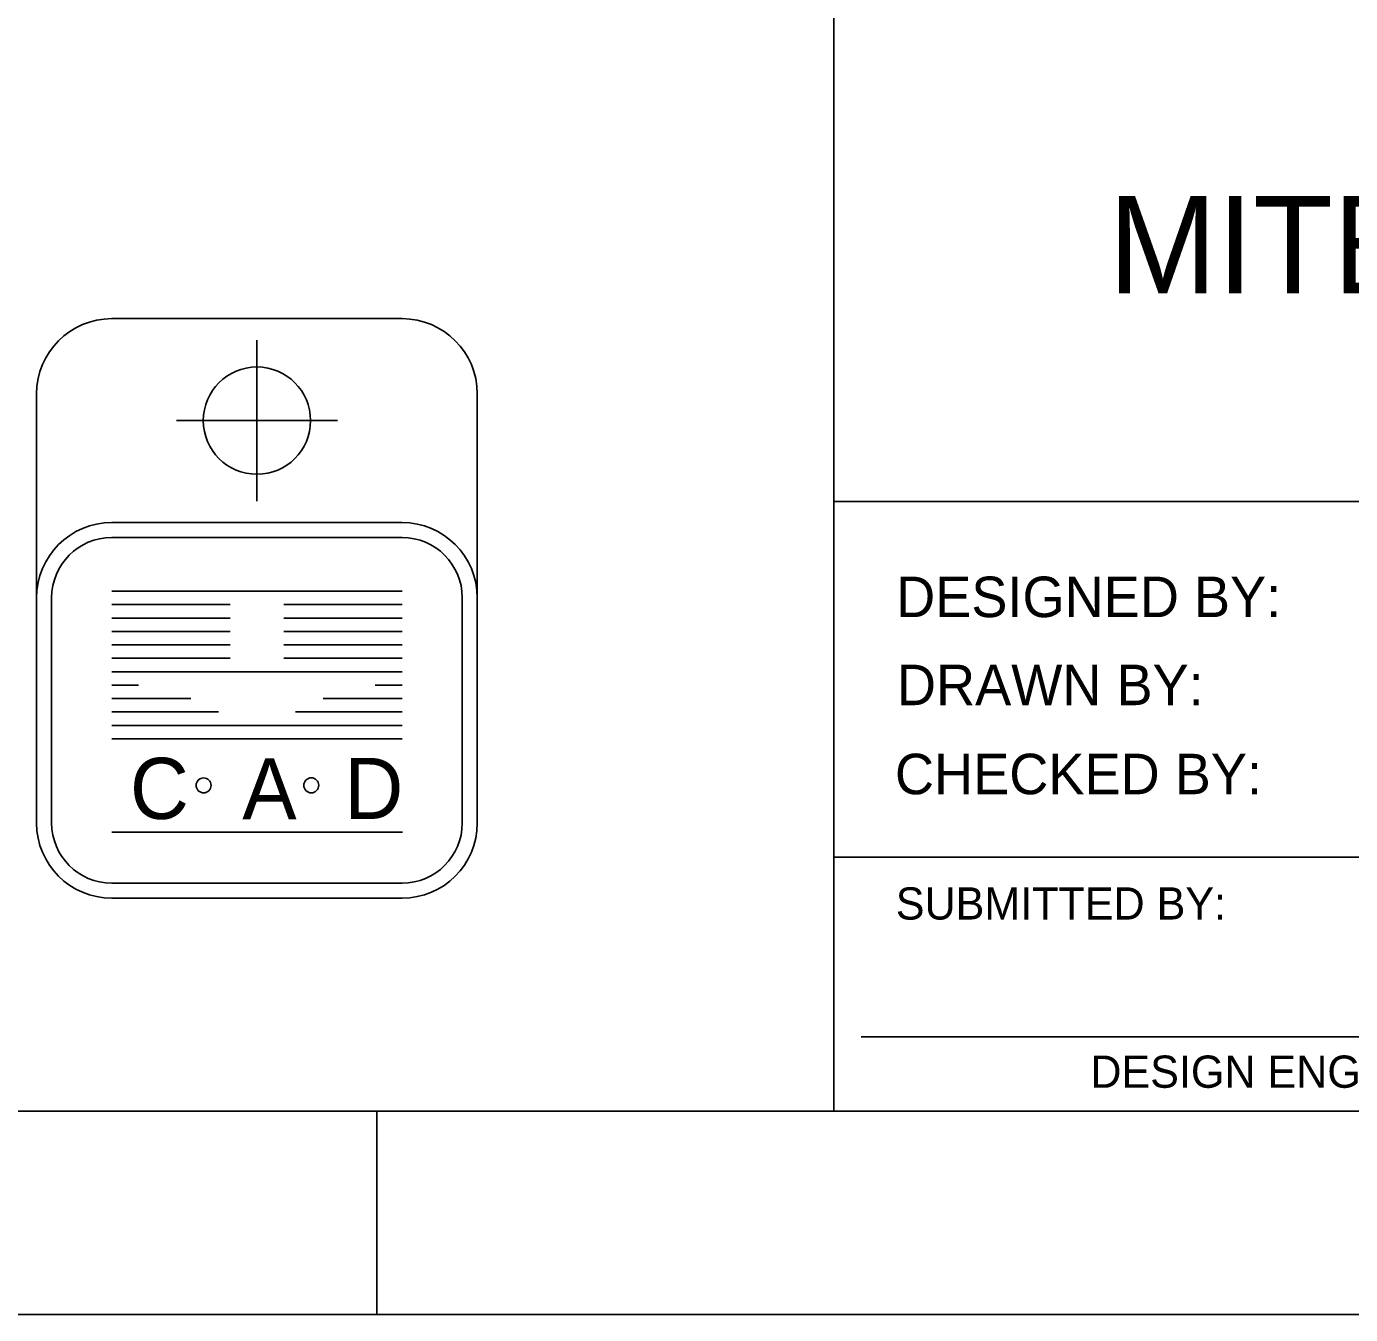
# Model space of a CAD drawing. Extents: x 0.04 to 6.71, y 0.04 to 4.71.
# Drawn here: x 5.211 to 5.754, y 0.042 to 0.57 of the extents above; entities that cross this region are included whole.
import ezdxf

# ---------------------------------------------------------------- set-up
doc = ezdxf.new("R2010")
doc.units = 0
doc.layers.add('Level 1', color=7, linetype='Continuous')
doc.layers.add('Level 2', color=7, linetype='Continuous')

msp = doc.modelspace()

# ---------------------------------------------------------------- linework, layer by layer
at = {"layer": 'Level 1'}
for p, q in [((5.54167, 0.125), (5.54167, 0.91667)), ((5.24551, 0.44998), (5.36461, 0.44998)), ((5.30505, 0.44119), (5.30505, 0.37519)), ((5.21472, 0.24317), (5.21472, 0.41919)), ((5.39543, 0.24317), (5.39543, 0.41919)), ((5.27205, 0.40819), (5.33805, 0.40819)), ((6.625, 0.375), (5.54167, 0.375)), ((5.24551, 0.36638), (5.36461, 0.36638)), ((5.24551, 0.36023), (5.36461, 0.36023)), ((5.24551, 0.33823), (5.36461, 0.33823)), ((5.22086, 0.24317), (5.22086, 0.33558)), ((5.24551, 0.33273), (5.29405, 0.33273)), ((5.31605, 0.33273), (5.36461, 0.33273)), ((5.38926, 0.24317), (5.38926, 0.33558)), ((5.24551, 0.32723), (5.29405, 0.32723)), ((5.31605, 0.32723), (5.36461, 0.32723)), ((5.24551, 0.32173), (5.29405, 0.32173)), ((5.31605, 0.32173), (5.36461, 0.32173)), ((5.24551, 0.31621), (5.29405, 0.31621)), ((5.31605, 0.31621), (5.36461, 0.31621)), ((5.24551, 0.31071), (5.29405, 0.31071)), ((5.31605, 0.31071), (5.36461, 0.31071)), ((5.24551, 0.30521), (5.36461, 0.30521)), ((5.24551, 0.29971), (5.25651, 0.29971)), ((5.36459, 0.29971), (5.35359, 0.29971)), ((5.24551, 0.29421), (5.27797, 0.29421)), ((5.36459, 0.29421), (5.33216, 0.29421)), ((5.24551, 0.28871), (5.28924, 0.28871)), ((5.36459, 0.28871), (5.32086, 0.28871)), ((5.24551, 0.28321), (5.36461, 0.28321)), ((5.24551, 0.27771), (5.36461, 0.27771)), ((5.24551, 0.2395), (5.36482, 0.2395)), ((5.54167, 0.22917), (5.91667, 0.22917)), ((5.24551, 0.21852), (5.36461, 0.21852)), ((5.24551, 0.21238), (5.36461, 0.21238)), ((5.55288, 0.15556), (5.90338, 0.15556)), ((5.35417, 0.125), (5.35417, 0.04167))]:
    msp.add_line(p, q, dxfattribs=at)
for points in [[(0.04167, 4.70833), (6.70833, 4.70833), (6.70833, 0.04167), (0.04167, 0.04167)], [(0.29167, 4.625), (6.625, 4.625), (6.625, 0.125), (0.29167, 0.125)]]:
    msp.add_lwpolyline(points, close=True, dxfattribs=at)
for centre, radius in [((5.30506, 0.40817), 0.022), ((5.28321, 0.25862), 0.00308), ((5.32735, 0.25864), 0.00308)]:
    msp.add_circle(centre, radius, dxfattribs=at)
for centre, radius, start, end in [((5.24552, 0.41917), 0.0308, 90, 180), ((5.36461, 0.41917), 0.0308, 0, 90), ((5.24552, 0.33557), 0.0308, 90, 180), ((5.36461, 0.33557), 0.0308, 0, 90), ((5.24552, 0.33557), 0.02464, 90, 180), ((5.36461, 0.33557), 0.02464, 0, 90), ((5.24552, 0.24317), 0.0308, 180, 270), ((5.24552, 0.24317), 0.02464, 180, 270), ((5.36461, 0.24317), 0.0308, 270, 360), ((5.36461, 0.24317), 0.02464, 270, 360)]:
    msp.add_arc(centre, radius, start, end, dxfattribs=at)

# ---------------------------------------------------------------- texts
for s, height, p in [('DESIGNED BY:', 0.0166041, (5.56717, 0.3276)), ('DRAWN BY:', 0.016604, (5.5675, 0.2915)), ('CHECKED BY:', 0.0166041, (5.56669, 0.25498)), ('C', 0.02505, (5.25299, 0.24485)), ('A', 0.02505, (5.29903, 0.24465)), ('D', 0.02505, (5.34091, 0.24485)), ('SUBMITTED BY:', 0.0132084, (5.56704, 0.2036)), ('DESIGN ENGINEER', 0.0132084, (5.64683, 0.13463))]:
    msp.add_text(s, height=height, dxfattribs=at).set_placement(p)
at = {"layer": 'Level 2'}
msp.add_text('MITER SWING GATE DETAILS', height=0.04, dxfattribs=at).set_placement((5.65419, 0.46033))

doc.saveas('drawing.dxf')
